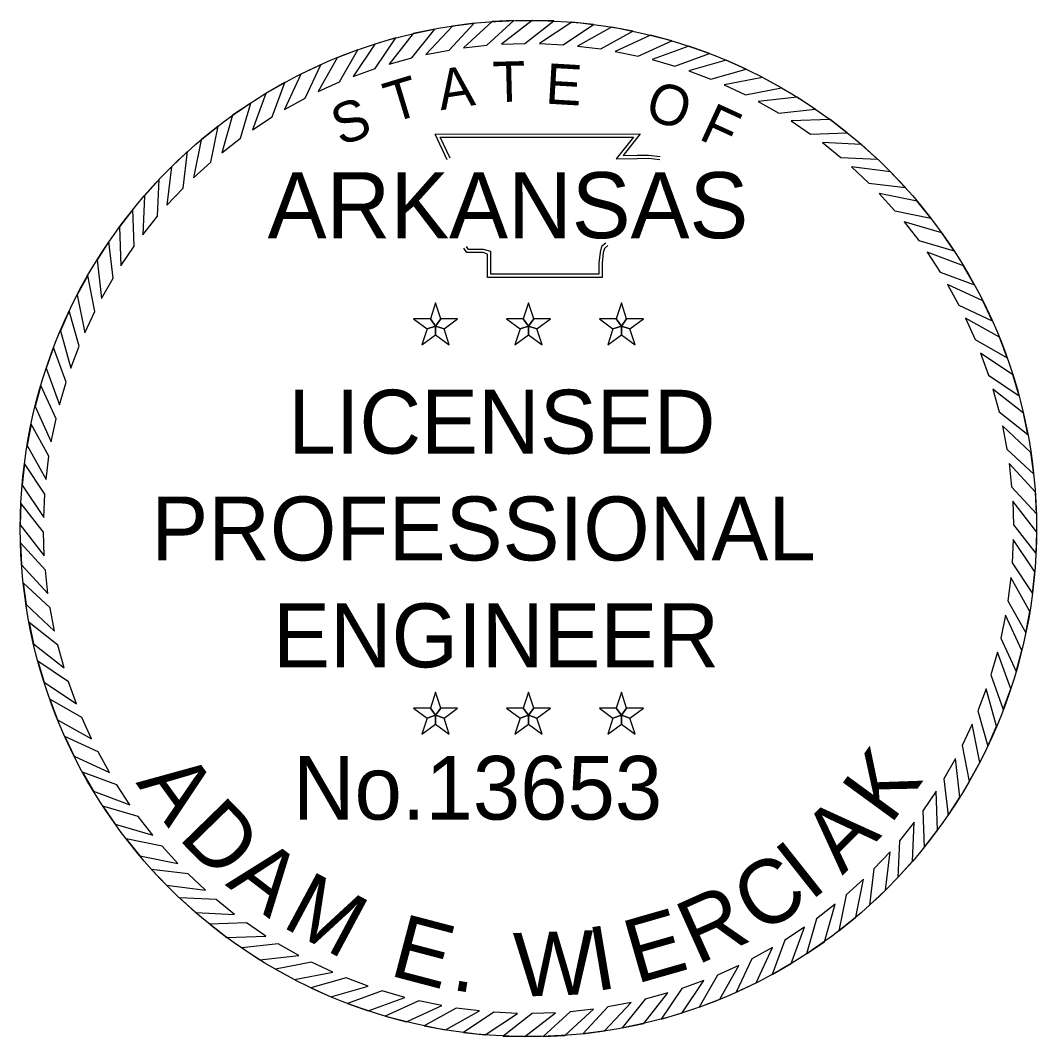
# Model space of a CAD drawing. Extents: x 0 to 19, y -0.6 to 11.2.
# Drawn here: x 17.822 to 19.022, y 4.919 to 6.119 of the extents above; entities that cross this region are included whole.
import ezdxf

# ---------------------------------------------------------------- set-up
doc = ezdxf.new("R2010")
doc.units = 0
doc.layers.add('G-ANNO-STMP', color=7, linetype='Continuous')
doc.layers.add('G-No Plot-Stamp-1', color=7, linetype='Continuous')

msp = doc.modelspace()

# ---------------------------------------------------------------- linework, layer by layer
at = {"layer": 'G-ANNO-STMP'}
for points in [[(18.3115, 6.1087), (18.2862, 6.1034), (18.2576, 6.0674), (18.2845, 6.0748)], [(18.3581, 6.1156), (18.3325, 6.1123), (18.3011, 6.0787), (18.3285, 6.0839)], [(18.4051, 6.1188), (18.3793, 6.1175), (18.3454, 6.0864), (18.3731, 6.0895)], [(18.4522, 6.1183), (18.4264, 6.119), (18.3902, 6.0907), (18.418, 6.0916)], [(18.4991, 6.1141), (18.4735, 6.1168), (18.4351, 6.0915), (18.463, 6.0902)], [(18.5456, 6.1062), (18.5202, 6.111), (18.48, 6.0887), (18.5077, 6.0852)], [(18.2656, 6.0982), (18.2408, 6.0909), (18.2151, 6.0528), (18.2413, 6.0623)], [(18.5913, 6.0947), (18.5664, 6.1015), (18.5245, 6.0824), (18.5518, 6.0768)], [(18.6359, 6.0797), (18.6116, 6.0884), (18.5684, 6.0726), (18.5952, 6.0649)], [(18.2206, 6.0841), (18.1965, 6.0749), (18.1738, 6.0349), (18.1992, 6.0464)], [(18.1769, 6.0666), (18.1536, 6.0555), (18.1341, 6.0138), (18.1585, 6.0273)], [(18.6793, 6.0612), (18.6557, 6.0718), (18.6114, 6.0595), (18.6375, 6.0496)], [(18.721, 6.0394), (18.6984, 6.0517), (18.6532, 6.043), (18.6784, 6.0311)], [(18.1347, 6.0456), (18.1123, 6.0328), (18.0962, 5.9897), (18.1195, 6.005)], [(18.7609, 6.0143), (18.7393, 6.0284), (18.6936, 6.0232), (18.7178, 6.0094)], [(18.0942, 6.0214), (18.0729, 6.0069), (18.0603, 5.9627), (18.0823, 5.9798)], [(18.7987, 5.9862), (18.7783, 6.002), (18.7323, 6.0004), (18.7554, 5.9847)], [(18.0558, 5.9942), (18.0357, 5.978), (18.0266, 5.9329), (18.0472, 5.9517)], [(18.8342, 5.9552), (18.8151, 5.9726), (18.7692, 5.9746), (18.7909, 5.9571)], [(18.0197, 5.964), (18.0009, 5.9462), (17.9953, 5.9006), (18.0144, 5.9209)], [(18.8672, 5.9216), (18.8495, 5.9403), (18.8038, 5.9459), (18.8242, 5.9269)], [(17.986, 5.931), (17.9687, 5.9119), (17.9667, 5.8659), (17.9841, 5.8877)], [(18.8974, 5.8854), (18.8812, 5.9055), (18.8361, 5.9147), (18.8549, 5.8941)], [(17.955, 5.8955), (17.9393, 5.8751), (17.9409, 5.8291), (17.9565, 5.8522)], [(18.9247, 5.847), (18.9101, 5.8683), (18.8659, 5.881), (18.883, 5.859)], [(17.9269, 5.8577), (17.9128, 5.8361), (17.918, 5.7904), (17.9318, 5.8146)], [(18.9489, 5.8066), (18.936, 5.829), (18.893, 5.8451), (18.9083, 5.8218)], [(17.9019, 5.8178), (17.8895, 5.7951), (17.8983, 5.75), (17.9102, 5.7752)], [(18.9698, 5.7644), (18.9588, 5.7877), (18.9171, 5.8071), (18.9305, 5.7827)], [(18.3125, 5.7579), (18.3187, 5.7664), (18.3125, 5.7854), (18.3064, 5.7664)], [(18.4222, 5.7579), (18.4284, 5.7664), (18.4222, 5.7854), (18.4161, 5.7664)], [(18.532, 5.7579), (18.5381, 5.7664), (18.532, 5.7854), (18.5258, 5.7664)], [(17.88, 5.776), (17.8695, 5.7525), (17.8818, 5.7082), (17.8916, 5.7342)], [(18.3125, 5.7579), (18.3064, 5.7664), (18.2864, 5.7664), (18.3026, 5.7547)], [(18.3125, 5.7579), (18.3225, 5.7547), (18.3386, 5.7664), (18.3187, 5.7664)], [(18.4222, 5.7579), (18.4161, 5.7664), (18.3962, 5.7664), (18.4123, 5.7547)], [(18.4222, 5.7579), (18.4322, 5.7547), (18.4483, 5.7664), (18.4284, 5.7664)], [(18.532, 5.7579), (18.5258, 5.7664), (18.5059, 5.7664), (18.522, 5.7547)], [(18.532, 5.7579), (18.5419, 5.7547), (18.5581, 5.7664), (18.5381, 5.7664)], [(18.9874, 5.7207), (18.9782, 5.7448), (18.9382, 5.7674), (18.9496, 5.742)], [(18.3125, 5.7579), (18.3026, 5.7547), (18.2964, 5.7357), (18.3125, 5.7475)], [(18.3125, 5.7579), (18.3125, 5.7475), (18.3286, 5.7357), (18.3225, 5.7547)], [(18.4222, 5.7579), (18.4123, 5.7547), (18.4061, 5.7357), (18.4222, 5.7475)], [(18.4222, 5.7579), (18.4222, 5.7475), (18.4384, 5.7357), (18.4322, 5.7547)], [(18.532, 5.7579), (18.522, 5.7547), (18.5158, 5.7357), (18.532, 5.7475)], [(18.532, 5.7579), (18.532, 5.7475), (18.5481, 5.7357), (18.5419, 5.7547)], [(17.8615, 5.7327), (17.8529, 5.7084), (17.8686, 5.6652), (17.8764, 5.6919)], [(19.0015, 5.6757), (18.9942, 5.7005), (18.9561, 5.7262), (18.9655, 5.6999)], [(17.8465, 5.688), (17.8398, 5.6631), (17.8588, 5.6213), (17.8645, 5.6486)], [(19.012, 5.6298), (19.0067, 5.655), (18.9707, 5.6837), (18.978, 5.6568)], [(17.835, 5.6423), (17.8303, 5.617), (17.8526, 5.5768), (17.856, 5.6044)], [(19.0188, 5.5832), (19.0155, 5.6087), (18.9819, 5.6401), (18.9871, 5.6127)], [(17.8272, 5.5959), (17.8244, 5.5702), (17.8498, 5.5319), (17.8511, 5.5597)], [(19.022, 5.5362), (19.0207, 5.5619), (18.9897, 5.5958), (18.9927, 5.5681)], [(17.823, 5.549), (17.8222, 5.5232), (17.8505, 5.4869), (17.8497, 5.5148)], [(19.0215, 5.489), (19.0223, 5.5148), (18.994, 5.5511), (18.9948, 5.5232)], [(17.8225, 5.5019), (17.8237, 5.4761), (17.8548, 5.4422), (17.8518, 5.4699)], [(19.0173, 5.4421), (19.0201, 5.4678), (18.9947, 5.5061), (18.9934, 5.4783)], [(19.0095, 5.3957), (19.0142, 5.421), (18.9919, 5.4612), (18.9884, 5.4336)], [(17.8256, 5.4548), (17.829, 5.4293), (17.8626, 5.3979), (17.8574, 5.4253)], [(18.998, 5.35), (19.0047, 5.3749), (18.9856, 5.4167), (18.98, 5.3894)], [(17.8325, 5.4082), (17.8378, 5.383), (17.8738, 5.3544), (17.8665, 5.3812)], [(18.9829, 5.3053), (18.9916, 5.3296), (18.9759, 5.3728), (18.9681, 5.3461)], [(17.843, 5.3623), (17.8503, 5.3376), (17.8884, 5.3118), (17.879, 5.3381)], [(18.9645, 5.262), (18.975, 5.2855), (18.9627, 5.3298), (18.9529, 5.3038)], [(17.8571, 5.3173), (17.8663, 5.2932), (17.9063, 5.2706), (17.8949, 5.296)], [(18.3125, 5.2985), (18.3187, 5.307), (18.3125, 5.3259), (18.3064, 5.307)], [(18.4222, 5.2985), (18.4284, 5.307), (18.4222, 5.3259), (18.4161, 5.307)], [(18.532, 5.2985), (18.5381, 5.307), (18.532, 5.3259), (18.5258, 5.307)], [(18.3125, 5.2985), (18.3064, 5.307), (18.2864, 5.307), (18.3026, 5.2952)], [(18.3125, 5.2985), (18.3225, 5.2952), (18.3386, 5.307), (18.3187, 5.307)], [(18.4222, 5.2985), (18.4161, 5.307), (18.3962, 5.307), (18.4123, 5.2952)], [(18.4222, 5.2985), (18.4322, 5.2952), (18.4483, 5.307), (18.4284, 5.307)], [(18.532, 5.2985), (18.5258, 5.307), (18.5059, 5.307), (18.522, 5.2952)], [(18.532, 5.2985), (18.5419, 5.2952), (18.5581, 5.307), (18.5381, 5.307)], [(18.3125, 5.2985), (18.3026, 5.2952), (18.2964, 5.2763), (18.3125, 5.288)], [(18.3125, 5.2985), (18.3125, 5.288), (18.3286, 5.2763), (18.3225, 5.2952)], [(18.4222, 5.2985), (18.4123, 5.2952), (18.4061, 5.2763), (18.4222, 5.288)], [(18.4222, 5.2985), (18.4222, 5.288), (18.4384, 5.2763), (18.4322, 5.2952)], [(18.532, 5.2985), (18.522, 5.2952), (18.5158, 5.2763), (18.532, 5.288)], [(18.532, 5.2985), (18.532, 5.288), (18.5481, 5.2763), (18.5419, 5.2952)], [(18.9426, 5.2202), (18.955, 5.2429), (18.9462, 5.288), (18.9343, 5.2628)], [(17.8747, 5.2736), (17.8857, 5.2503), (17.9274, 5.2309), (17.914, 5.2553)], [(18.9176, 5.1803), (18.9317, 5.2019), (18.9265, 5.2476), (18.9127, 5.2234)], [(17.8956, 5.2314), (17.9085, 5.209), (17.9515, 5.1929), (17.9362, 5.2162)], [(18.8895, 5.1425), (18.9052, 5.1629), (18.9036, 5.2089), (18.888, 5.1858)], [(17.9198, 5.191), (17.9344, 5.1697), (17.9786, 5.157), (17.9615, 5.179)], [(18.8585, 5.107), (18.8758, 5.1261), (18.8778, 5.1721), (18.8604, 5.1503)], [(17.9471, 5.1526), (17.9633, 5.1325), (18.0083, 5.1233), (17.9896, 5.1439)], [(18.8248, 5.0741), (18.8436, 5.0918), (18.8492, 5.1374), (18.8301, 5.1171)], [(17.9773, 5.1164), (17.995, 5.0977), (18.0407, 5.0921), (18.0203, 5.1111)], [(18.7887, 5.0438), (18.8088, 5.06), (18.8179, 5.1051), (18.7973, 5.0863)], [(18.0103, 5.0828), (18.0294, 5.0654), (18.0753, 5.0634), (18.0536, 5.0809)], [(18.7503, 5.0166), (18.7716, 5.0311), (18.7842, 5.0753), (18.7622, 5.0582)], [(18.0458, 5.0518), (18.0662, 5.036), (18.1122, 5.0376), (18.0891, 5.0533)], [(18.7098, 4.9924), (18.7322, 5.0052), (18.7483, 5.0483), (18.725, 5.033)], [(18.0836, 5.0237), (18.1052, 5.0096), (18.1509, 5.0148), (18.1267, 5.0286)], [(18.6676, 4.9714), (18.6909, 4.9825), (18.7104, 5.0242), (18.6859, 5.0107)], [(18.1235, 4.9986), (18.1461, 4.9863), (18.1913, 4.995), (18.166, 5.0069)], [(18.6239, 4.9539), (18.648, 4.9631), (18.6707, 5.0031), (18.6453, 4.9916)], [(18.1652, 4.9768), (18.1888, 4.9662), (18.2331, 4.9785), (18.207, 4.9884)], [(18.5789, 4.9398), (18.6037, 4.9471), (18.6294, 4.9852), (18.6032, 4.9757)], [(18.2086, 4.9583), (18.2329, 4.9496), (18.2761, 4.9654), (18.2493, 4.9731)], [(18.533, 4.9293), (18.5583, 4.9346), (18.5869, 4.9706), (18.56, 4.9632)], [(18.2532, 4.9433), (18.2781, 4.9365), (18.32, 4.9556), (18.2927, 4.9612)], [(18.4864, 4.9224), (18.512, 4.9257), (18.5434, 4.9593), (18.516, 4.9541)], [(18.2989, 4.9318), (18.3243, 4.927), (18.3645, 4.9493), (18.3368, 4.9528)], [(18.3454, 4.9239), (18.371, 4.9212), (18.4094, 4.9465), (18.3815, 4.9478)], [(18.3923, 4.9197), (18.4181, 4.919), (18.4543, 4.9473), (18.4265, 4.9464)], [(18.4394, 4.9192), (18.4652, 4.9205), (18.4991, 4.9516), (18.4714, 4.9485)]]:
    msp.add_lwpolyline(points, close=True, dxfattribs=at)
for points in [[(18.3261, 5.9545), (18.3121, 5.9848), (18.5542, 5.9849), (18.5339, 5.9595), (18.5504, 5.9597), (18.5641, 5.9599), (18.5778, 5.9584)], [(18.3296, 5.9561), (18.3181, 5.981), (18.5462, 5.9811), (18.5259, 5.9556), (18.5504, 5.9559), (18.5639, 5.9561), (18.5774, 5.9546)], [(18.516, 5.8531), (18.5119, 5.8497), (18.5105, 5.8447), (18.5091, 5.8322), (18.5091, 5.8154), (18.374, 5.8154), (18.374, 5.838), (18.374, 5.843), (18.3686, 5.8447), (18.3493, 5.8447), (18.3459, 5.8499)], [(18.5136, 5.856), (18.5085, 5.8519), (18.5067, 5.8454), (18.5053, 5.8324), (18.5053, 5.8193), (18.3779, 5.8193), (18.3779, 5.838), (18.3779, 5.8459), (18.3691, 5.8485), (18.3514, 5.8485), (18.3491, 5.852)]]:
    msp.add_lwpolyline(points, dxfattribs=at)
at = {"layer": 'G-No Plot-Stamp-1'}
msp.add_circle((18.4222, 5.519), 0.6, dxfattribs=at)

# ---------------------------------------------------------------- texts
at = {"layer": 'G-ANNO-STMP'}
for s, height, rotation, p in [('A', 0.0477, 8.6788, (18.3187, 6.0128)), ('T', 0.0477, 1.4789, (18.3804, 6.0223)), ('E', 0.0477, 356.672, (18.4415, 6.0208)), ('T', 0.0477, 16.9015, (18.2608, 5.9976)), ('O', 0.0477, 341.2218, (18.5574, 6.0044)), ('S', 0.0477, 19.7726, (18.2001, 5.9704)), ('F', 0.0477, 335.3628, (18.6218, 5.9793)), ('K', 0.0754, 53.8471, (18.8495, 5.1679)), ('A', 0.0754, 305.982, (17.958, 5.2187)), ('D', 0.0754, 314.3022, (18.0075, 5.1535)), ('A', 0.0754, 45.185, (18.7929, 5.1088)), ('I', 0.0754, 38.4057, (18.7549, 5.0781)), ('A', 0.0754, 322.6223, (18.0634, 5.0983)), ('C', 0.0754, 32.1396, (18.695, 5.0383)), ('M', 0.0754, 331.7969, (18.1293, 5.0496)), ('R', 0.0754, 24.1616, (18.6211, 5.0031)), ('E', 0.0754, 16.0125, (18.5491, 4.981)), ('E', 0.0754, 345.2782, (18.2564, 4.9917)), ('W', 0.0754, 2.1127, (18.4063, 4.9659)), ('I', 0.0754, 9.5753, (18.5011, 4.9724)), ('.', 0.0754, 350.8583, (18.3296, 4.9747))]:
    msp.add_text(s, height=height, rotation=rotation, dxfattribs=at).set_placement(p)
for s, height, p in [('ARKANSAS', 0.07792, (18.1143, 5.8618)), ('LICENSED', 0.07543, (18.1385, 5.6074)), ('PROFESSIONAL', 0.075433, (17.9768, 5.4813)), ('ENGINEER', 0.07543, (18.1205, 5.3551)), ('No.13653', 0.07514, (18.1443, 5.1753))]:
    msp.add_text(s, height=height, dxfattribs=at).set_placement(p)

doc.saveas('drawing.dxf')
